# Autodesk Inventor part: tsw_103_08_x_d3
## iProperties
Created: 2006-03
Part Number: tsw_103_08_x_d3
Document SubType Name: Modeling
Designer: Elise Moss
Author: Elise Moss
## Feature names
1. Base1
